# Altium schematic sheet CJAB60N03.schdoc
size 127 x 101 mm
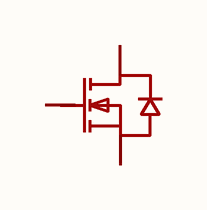
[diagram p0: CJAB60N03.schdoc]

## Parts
Q?  cjab60n03  [PDFNWB-8_L3.0-W3.0-P0.65-BL]  (value not drawn)

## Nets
NetQ?_1: Q?.1(S) Q?.2(S) Q?.3(S)
NetQ?_5: Q?.5(D) Q?.6(D) Q?.7(D) Q?.8(D) Q?.9(D)

Not connected (* = marked no-connect by the designer): Q? 4(G)

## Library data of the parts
Q? = cjab60n03: 数量:1个N沟道;漏源电压(Vdss):30V;连续漏极电流(Id):60A;导通电阻(RDS(on)):7.3mΩ@4.5V;耗散功率(Pd):1.5W;阈值电压(Vgs(th)):1V;; Manufacturer: CJ(江苏长电/长晶); AddInBom: yes; ModelId: 25c07daa3c6f4a09b1bedbcc3b730fbb; ModelName: PDFNWB-8_L3.0-W3.0-H0.8-P0.65-BL; ModelTransform: 122.047,129.921,0,180,0,0,0,0,0; Number: 1个N沟道; Drain to Source Voltage: 30V; Current - Continuous Drain(Id): 60A; Pd - Power Dissipation: 1.5W; Gate Threshold Voltage (Vgs(th)): 1V; Gate Charge(Qg): 61.2nC@10V; Input Capacitance(Ciss): 3.198nF; Reverse Transfer Capacitance (Crss@Vds): 485pF; Type: N沟道; Vgs: ±20V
